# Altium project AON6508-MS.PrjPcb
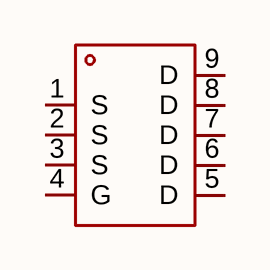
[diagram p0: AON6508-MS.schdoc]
1 sheet, 1 parts. Net scope: global (net labels, ports and power ports of the same name join across sheets).

## Sheet AON6508-MS.schdoc
size 127 x 101 mm

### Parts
Q?  aon6508-ms  [PDFN-8_L4.9-W5.8-P1.27-LS6.1-BL]  (value not drawn)

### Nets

Not connected (* = marked no-connect by the designer): Q? 1(S) 2(S) 3(S) 4(G) 5(D) 6(D) 7(D) 8(D) 9(D)

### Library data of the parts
Q? = aon6508-ms: 数量:1个N沟道;漏源电压(Vdss):30V;连续漏极电流(Id):150A;导通电阻(RDS(on)):2mΩ@10V;耗散功率(Pd):187W;阈值电压(Vgs(th)):1.2V;; Manufacturer: MSKSEMI(美森科); AddInBom: yes; ModelId: 178189b27e7544aca50c111426555358; ModelName: PDFN-8_L4.9-W5.8-H1.0-P1.27; ModelTransform: 200.787,240.157,0,0,0,0,-0.097,0,0; Number: 1个N沟道; Drain to Source Voltage: 30V; Current - Continuous Drain(Id): 150A; Pd - Power Dissipation: 187W; Gate Threshold Voltage (Vgs(th)): 1.2V; Gate Charge(Qg): 56.9nC; Input Capacitance(Ciss): 4.345nF; Reverse Transfer Capacitance (Crss@Vds): 225pF; Type: N沟道; Output Capacitance(Coss): 340pF; Vgs: ±20V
